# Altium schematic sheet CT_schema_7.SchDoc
size 287 x 160 mm
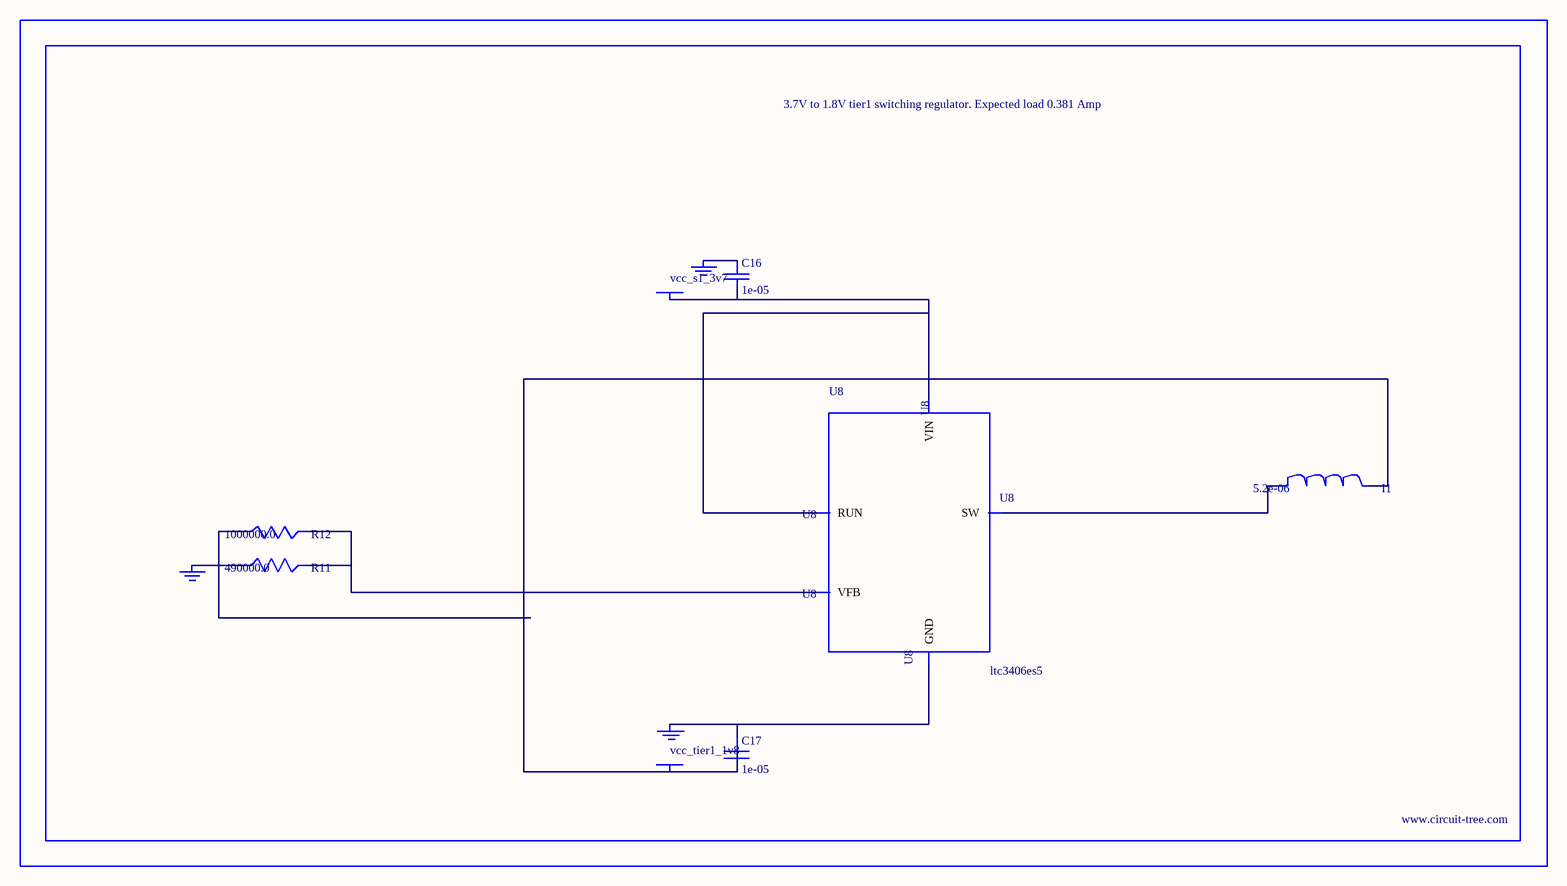
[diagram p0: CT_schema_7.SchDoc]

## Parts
BORDER6  (no value)
C16  1e-05  [C0805]
C17  1e-05  [C0805]
GND_INSTANCE_6_0  (no value)
GND_INSTANCE_6_1  (no value)
GND_INSTANCE_6_2  (no value)
I1  5.2e-06  [DR1040]
POWER_INSTANCE_6_0  vcc_tier1_1v8
POWER_INSTANCE_6_1  vcc_s1_3v7
R11  490000.0  [R0603]
R12  1000000.0  [R0603]
U8  ltc3406es5  [TSOT-23-5]

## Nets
NetC16_1: C16.1 GND_INSTANCE_6_1.0(GND)
NetC16_2: C16.2 POWER_INSTANCE_6_1.0(PWR) U8.1(RUN) U8.4(VIN)
NetC17_1: C17.1 GND_INSTANCE_6_0.0(GND) U8.2(GND)
NetC17_2: C17.2 I1.2 POWER_INSTANCE_6_0.0(PWR) R12.1
NetGND_INSTANCE_6_2_0: GND_INSTANCE_6_2.0(GND) R11.1
NetI1_1: I1.1 U8.3(SW)
NetR11_2: R11.2 R12.2 U8.5(VFB)

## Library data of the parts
BORDER6 = BORDER_PAGE6
C16 C17 = C0805C106K8RACTU
GND_INSTANCE_6_0-GND_INSTANCE_6_2 = GND
I1 = DR1040-5R2-R
POWER_INSTANCE_6_0 POWER_INSTANCE_6_1 = PWR
R11 = R11
R12 = RC0603JR-071ML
